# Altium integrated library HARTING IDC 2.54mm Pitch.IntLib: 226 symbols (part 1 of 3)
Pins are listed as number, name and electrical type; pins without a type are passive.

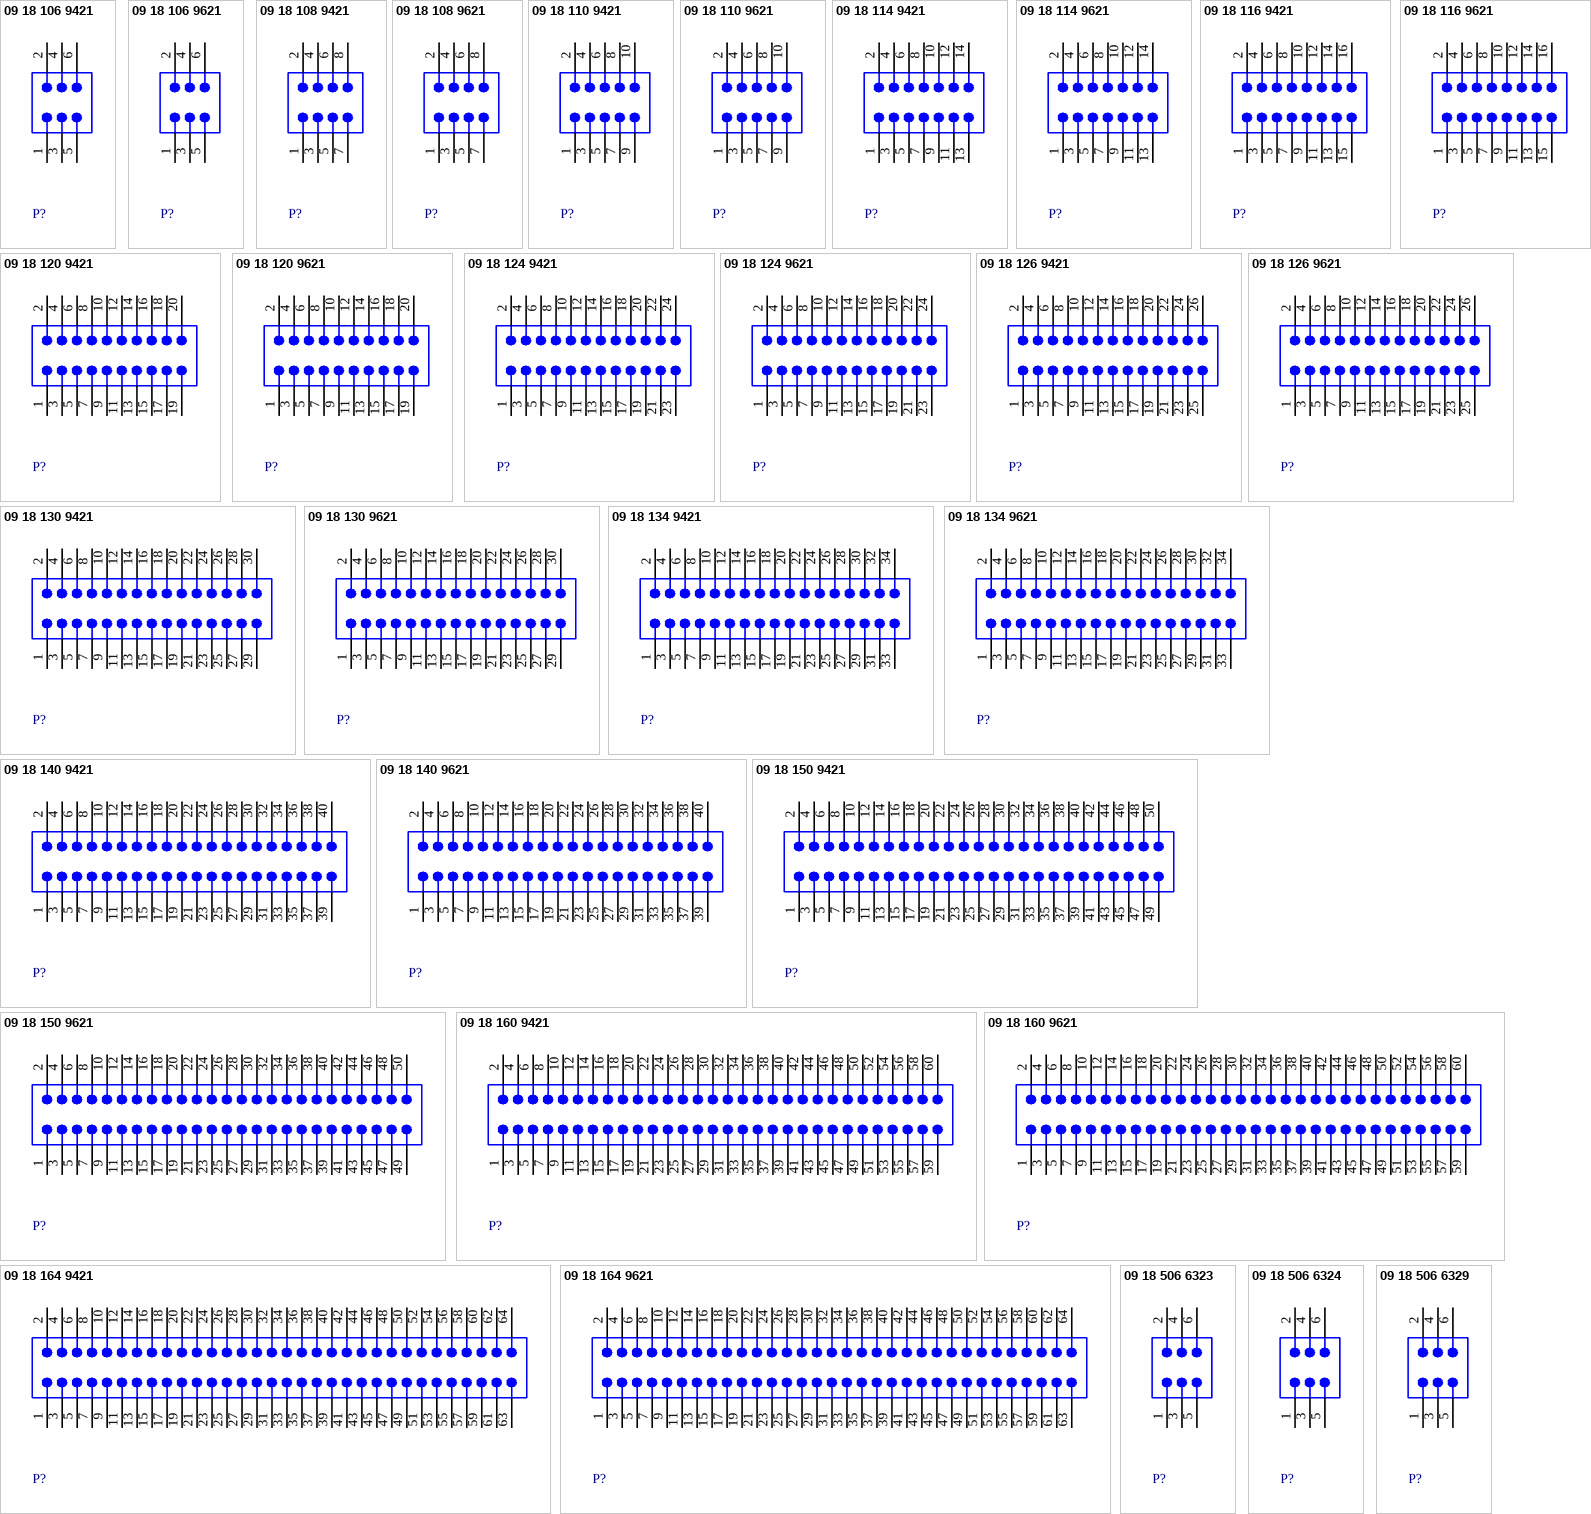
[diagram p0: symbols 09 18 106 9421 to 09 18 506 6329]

## 09 18 106 9421
designator P?
Flat Cable Connector (IDC), PCB Transition Connector, 2 Rows, Kinked Solder Pin, 6 Contacts; PCB_Layout: Complies with manufacturer's recommendation.; DrillSize: Corresponds to nominal value.
footprint 9181069421 (Connector; IDC, PCB Transition - 2 Rows, Thru-Hole; 6 Position; Vertical; Pitch 2.54 mm; Body 12.92 x 6.1 x 7.45 mm (LxWxH), Kinked Contacts)
pins: 1, 2, 3, 4, 5, 6

## 09 18 106 9621
designator P?
Flat Cable Connector (IDC), PCB Transition Connector, 2 Rows, Solder Pin, 6 Contacts; PCB_Layout: Complies with manufacturer's recommendation.; DrillSize: Corresponds to nominal value.
footprint 9181069621 (Connector; IDC, PCB Transition - 2 Rows, Thru-Hole; 6 Position; Vertical; Pitch 2.54 mm; Body 12.92 x 6.1 x 7.45 mm (LxWxH))
pins: 1, 2, 3, 4, 5, 6

## 09 18 108 9421
designator P?
Flat Cable Connector (IDC), PCB Transition Connector, 2 Rows, Kinked Solder Pin, 8 Contacts; PCB_Layout: Complies with manufacturer's recommendation.; DrillSize: Corresponds to nominal value.
footprint 9181089421 (Connector; IDC, PCB Transition - 2 Rows, Thru-Hole; 8 Position; Vertical; Pitch 2.54 mm; Body 15.46 x 6.1 x 7.45 mm (LxWxH), Kinked Contacts)
pins: 1, 2, 3, 4, 5, 6, 7, 8

## 09 18 108 9621
designator P?
Flat Cable Connector (IDC), PCB Transition Connector, 2 Rows, Solder Pin, 8 Contacts; PCB_Layout: Complies with manufacturer's recommendation.; DrillSize: Corresponds to nominal value.
footprint 9181089621 (Connector; IDC, PCB Transition - 2 Rows, Thru-Hole; 8 Position; Vertical; Pitch 2.54 mm; Body 15.46 x 6.1 x 7.45 mm (LxWxH))
pins: 1, 2, 3, 4, 5, 6, 7, 8

## 09 18 110 9421
designator P?
Flat Cable Connector (IDC), PCB Transition Connector, 2 Rows, Kinked Solder Pin, 10 Contacts; PCB_Layout: Complies with manufacturer's recommendation.; DrillSize: Corresponds to nominal value.
footprint 9181109421 (Connector; IDC, PCB Transition - 2 Rows, Thru-Hole; 10 Position; Vertical; Pitch 2.54 mm; Body 18.00 x 6.1 x 7.45 mm (LxWxH), Kinked Contacts)
pins: 1, 2, 3, 4, 5, 6, 7, 8, 9, 10

## 09 18 110 9621
designator P?
Flat Cable Connector (IDC), PCB Transition Connector, 2 Rows, Solder Pin, 10 Contacts; PCB_Layout: Complies with manufacturer's recommendation.; DrillSize: Corresponds to nominal value.
footprint 9181109621 (Connector; IDC, PCB Transition - 2 Rows, Thru-Hole; 10 Position; Vertical; Pitch 2.54 mm; Body 18.00 x 6.1 x 7.45 mm (LxWxH))
pins: 1, 2, 3, 4, 5, 6, 7, 8, 9, 10

## 09 18 114 9421
designator P?
Flat Cable Connector (IDC), PCB Transition Connector, 2 Rows, Kinked Solder Pin, 14 Contacts; PCB_Layout: Complies with manufacturer's recommendation.; DrillSize: Corresponds to nominal value.
footprint 9181149421 (Connector; IDC, PCB Transition - 2 Rows, Thru-Hole; 14 Position; Vertical; Pitch 2.54 mm; Body 23.08 x 6.1 x 7.45 mm (LxWxH), Kinked Contacts)
pins: 1, 2, 3, 4, 5, 6, 7, 8, 9, 10, 11, 12, 13, 14

## 09 18 114 9621
designator P?
Flat Cable Connector (IDC), PCB Transition Connector, 2 Rows, Solder Pin, 14 Contacts; PCB_Layout: Complies with manufacturer's recommendation.; DrillSize: Corresponds to nominal value.
footprint 9181149621 (Connector; IDC, PCB Transition - 2 Rows, Thru-Hole; 14 Position; Vertical; Pitch 2.54 mm; Body 23.08 x 6.1 x 7.45 mm (LxWxH))
pins: 1, 2, 3, 4, 5, 6, 7, 8, 9, 10, 11, 12, 13, 14

## 09 18 116 9421
designator P?
Flat Cable Connector (IDC), PCB Transition Connector, 2 Rows, Kinked Solder Pin, 16 Contacts; PCB_Layout: Complies with manufacturer's recommendation.; DrillSize: Corresponds to nominal value.
footprint 9181169421 (Connector; IDC, PCB Transition - 2 Rows, Thru-Hole; 16 Position; Vertical; Pitch 2.54 mm; Body 25.62 x 6.1 x 7.45 mm (LxWxH), Kinked Contacts)
pins: 1, 2, 3, 4, 5, 6, 7, 8, 9, 10, 11, 12, 13, 14, 15, 16

## 09 18 116 9621
designator P?
Flat Cable Connector (IDC), PCB Transition Connector, 2 Rows, Solder Pin, 16 Contacts; PCB_Layout: Complies with manufacturer's recommendation.; DrillSize: Corresponds to nominal value.
footprint 9181169621 (Connector; IDC, PCB Transition - 2 Rows, Thru-Hole; 16 Position; Vertical; Pitch 2.54 mm; Body 25.62 x 6.1 x 7.45 mm (LxWxH))
pins: 1, 2, 3, 4, 5, 6, 7, 8, 9, 10, 11, 12, 13, 14, 15, 16

## 09 18 120 9421
designator P?
Flat Cable Connector (IDC), PCB Transition Connector, 2 Rows, Kinked Solder Pin, 20 Contacts; PCB_Layout: Complies with manufacturer's recommendation.; DrillSize: Corresponds to nominal value.
footprint 9181209421 (Connector; IDC, PCB Transition - 2 Rows, Thru-Hole; 20 Position; Vertical; Pitch 2.54 mm; Body 30.74 x 6.1 x 7.45 mm (LxWxH), Kinked Contacts)
pins: 1, 2, 3, 4, 5, 6, 7, 8, 9, 10, 11, 12, 13, 14, 15, 16, 17, 18, 19, 20

## 09 18 120 9621
designator P?
Flat Cable Connector (IDC), PCB Transition Connector, 2 Rows, Solder Pin, 20 Contacts; PCB_Layout: Complies with manufacturer's recommendation.; DrillSize: Corresponds to nominal value.
footprint 9181209621 (Connector; IDC, PCB Transition - 2 Rows, Thru-Hole; 20 Position; Vertical; Pitch 2.54 mm; Body 30.74 x 6.1 x 7.45 mm (LxWxH))
pins: 1, 2, 3, 4, 5, 6, 7, 8, 9, 10, 11, 12, 13, 14, 15, 16, 17, 18, 19, 20

## 09 18 124 9421
designator P?
Flat Cable Connector (IDC), PCB Transition Connector, 2 Rows, Kinked Solder Pin, 24 Contacts; PCB_Layout: Complies with manufacturer's recommendation.; DrillSize: Corresponds to nominal value.
footprint 9181249421 (Connector; IDC, PCB Transition - 2 Rows, Thru-Hole; 24 Position; Vertical; Pitch 2.54 mm; Body 35.78 x 6.1 x 7.45 mm (LxWxH), Kinked Contacts)
pins: 1, 2, 3, 4, 5, 6, 7, 8, 9, 10, 11, 12, 13, 14, 15, 16, 17, 18, 19, 20, 21, 22, 23, 24

## 09 18 124 9621
designator P?
Flat Cable Connector (IDC), PCB Transition Connector, 2 Rows, Solder Pin, 24 Contacts; PCB_Layout: Complies with manufacturer's recommendation.; DrillSize: Corresponds to nominal value.
footprint 9181249621 (Connector; IDC, PCB Transition - 2 Rows, Thru-Hole; 24 Position; Vertical; Pitch 2.54 mm; Body 35.78 x 6.1 x 7.45 mm (LxWxH))
pins: 1, 2, 3, 4, 5, 6, 7, 8, 9, 10, 11, 12, 13, 14, 15, 16, 17, 18, 19, 20, 21, 22, 23, 24

## 09 18 126 9421
designator P?
Flat Cable Connector (IDC), PCB Transition Connector, 2 Rows, Kinked Solder Pin, 26 Contacts; PCB_Layout: Complies with manufacturer's recommendation.; DrillSize: Corresponds to nominal value.
footprint 9181269421 (Connector; IDC, PCB Transition - 2 Rows, Thru-Hole; 26 Position; Vertical; Pitch 2.54 mm; Body 38.32 x 6.1 x 7.45 mm (LxWxH), Kinked Contacts)
pins: 1, 2, 3, 4, 5, 6, 7, 8, 9, 10, 11, 12, 13, 14, 15, 16, 17, 18, 19, 20, 21, 22, 23, 24, 25, 26

## 09 18 126 9621
designator P?
Flat Cable Connector (IDC), PCB Transition Connector, 2 Rows, Solder Pin, 26 Contacts; PCB_Layout: Complies with manufacturer's recommendation.; DrillSize: Corresponds to nominal value.
footprint 9181269621 (Connector; IDC, PCB Transition - 2 Rows, Thru-Hole; 26 Position; Vertical; Pitch 2.54 mm; Body 38.32 x 6.1 x 7.45 mm (LxWxH))
pins: 1, 2, 3, 4, 5, 6, 7, 8, 9, 10, 11, 12, 13, 14, 15, 16, 17, 18, 19, 20, 21, 22, 23, 24, 25, 26

## 09 18 130 9421
designator P?
Flat Cable Connector (IDC), PCB Transition Connector, 2 Rows, Kinked Solder Pin, 30 Contacts; PCB_Layout: Complies with manufacturer's recommendation.; DrillSize: Corresponds to nominal value.
footprint 9181309421 (Connector; IDC, PCB Transition - 2 Rows, Thru-Hole; 30 Position; Vertical; Pitch 2.54 mm; Body 43.40 x 6.1 x 7.45 mm (LxWxH), Kinked Contacts)
pins: 1, 2, 3, 4, 5, 6, 7, 8, 9, 10, 11, 12, 13, 14, 15, 16, 17, 18, 19, 20, 21, 22, 23, 24, 25, 26, 27, 28, 29, 30

## 09 18 130 9621
designator P?
Flat Cable Connector (IDC), PCB Transition Connector, 2 Rows, Solder Pin, 30 Contacts; PCB_Layout: Complies with manufacturer's recommendation.; DrillSize: Corresponds to nominal value.
footprint 9181309621 (Connector; IDC, PCB Transition - 2 Rows, Thru-Hole; 30 Position; Vertical; Pitch 2.54 mm; Body 43.40 x 6.1 x 7.45 mm (LxWxH))
pins: 1, 2, 3, 4, 5, 6, 7, 8, 9, 10, 11, 12, 13, 14, 15, 16, 17, 18, 19, 20, 21, 22, 23, 24, 25, 26, 27, 28, 29, 30

## 09 18 134 9421
designator P?
Flat Cable Connector (IDC), PCB Transition Connector, 2 Rows, Kinked Solder Pin, 34 Contacts; PCB_Layout: Complies with manufacturer's recommendation.; DrillSize: Corresponds to nominal value.
footprint 9181349421 (Connector; IDC, PCB Transition - 2 Rows, Thru-Hole; 34 Position; Vertical; Pitch 2.54 mm; Body 48.48 x 6.1 x 7.45 mm (LxWxH), Kinked Contacts)
pins: 1, 2, 3, 4, 5, 6, 7, 8, 9, 10, 11, 12, 13, 14, 15, 16, 17, 18, 19, 20, 21, 22, 23, 24, 25, 26, 27, 28, 29, 30, 31, 32, 33, 34

## 09 18 134 9621
designator P?
Flat Cable Connector (IDC), PCB Transition Connector, 2 Rows, Solder Pin, 34 Contacts; PCB_Layout: Complies with manufacturer's recommendation.; DrillSize: Corresponds to nominal value.
footprint 9181349621 (Connector; IDC, PCB Transition - 2 Rows, Thru-Hole; 34 Position; Vertical; Pitch 2.54 mm; Body 48.48 x 6.1 x 7.45 mm (LxWxH))
pins: 1, 2, 3, 4, 5, 6, 7, 8, 9, 10, 11, 12, 13, 14, 15, 16, 17, 18, 19, 20, 21, 22, 23, 24, 25, 26, 27, 28, 29, 30, 31, 32, 33, 34

## 09 18 140 9421
designator P?
Flat Cable Connector (IDC), PCB Transition Connector, 2 Rows, Kinked Solder Pin, 40 Contacts; PCB_Layout: Complies with manufacturer's recommendation.; DrillSize: Corresponds to nominal value.
footprint 9181409421 (Connector; IDC, PCB Transition - 2 Rows, Thru-Hole; 40 Position; Vertical; Pitch 2.54 mm; Body 56.10 x 6.1 x 7.45 mm (LxWxH), Kinked Contacts)
pins: 1, 2, 3, 4, 5, 6, 7, 8, 9, 10, 11, 12, 13, 14, 15, 16, 17, 18, 19, 20, 21, 22, 23, 24, 25, 26, 27, 28, 29, 30, 31, 32, 33, 34, 35, 36, 37, 38, 39, 40

## 09 18 140 9621
designator P?
Flat Cable Connector (IDC), PCB Transition Connector, 2 Rows, Solder Pin, 40 Contacts; PCB_Layout: Complies with manufacturer's recommendation.; DrillSize: Corresponds to nominal value.
footprint 9181409621 (Connector; IDC, PCB Transition - 2 Rows, Thru-Hole; 40 Position; Vertical; Pitch 2.54 mm; Body 56.10 x 6.1 x 7.45 mm (LxWxH))
pins: 1, 2, 3, 4, 5, 6, 7, 8, 9, 10, 11, 12, 13, 14, 15, 16, 17, 18, 19, 20, 21, 22, 23, 24, 25, 26, 27, 28, 29, 30, 31, 32, 33, 34, 35, 36, 37, 38, 39, 40

## 09 18 150 9421
designator P?
Flat Cable Connector (IDC), PCB Transition Connector, 2 Rows, Kinked Solder Pin, 50 Contacts; PCB_Layout: Complies with manufacturer's recommendation.; DrillSize: Corresponds to nominal value.
footprint 9181509421 (Connector; IDC, PCB Transition - 2 Rows, Thru-Hole; 50 Position; Vertical; Pitch 2.54 mm; Body 68.80 x 6.1 x 7.45 mm (LxWxH), Kinked Contacts)
pins: 1, 2, 3, 4, 5, 6, 7, 8, 9, 10, 11, 12, 13, 14, 15, 16, 17, 18, 19, 20, 21, 22, 23, 24, 25, 26, 27, 28, 29, 30, 31, 32, 33, 34, 35, 36, 37, 38, 39, 40, 41, 42, 43, 44, 45, 46, 47, 48, 49, 50

## 09 18 150 9621
designator P?
Flat Cable Connector (IDC), PCB Transition Connector, 2 Rows, Solder Pin, 50 Contacts; PCB_Layout: Complies with manufacturer's recommendation.; DrillSize: Corresponds to nominal value.
footprint 9181509621 (Connector; IDC, PCB Transition - 2 Rows, Thru-Hole; 50 Position; Vertical; Pitch 2.54 mm; Body 68.80 x 6.1 x 7.45 mm (LxWxH))
pins: 1, 2, 3, 4, 5, 6, 7, 8, 9, 10, 11, 12, 13, 14, 15, 16, 17, 18, 19, 20, 21, 22, 23, 24, 25, 26, 27, 28, 29, 30, 31, 32, 33, 34, 35, 36, 37, 38, 39, 40, 41, 42, 43, 44, 45, 46, 47, 48, 49, 50

## 09 18 160 9421
designator P?
Flat Cable Connector (IDC), PCB Transition Connector, 2 Rows, Kinked Solder Pin, 60 Contacts; PCB_Layout: Complies with manufacturer's recommendation.; DrillSize: Corresponds to nominal value.
footprint 9181609421 (Connector; IDC, PCB Transition - 2 Rows, Thru-Hole; 60 Position; Vertical; Pitch 2.54 mm; Body 81.50 x 6.1 x 7.45 mm (LxWxH), Kinked Contacts)
pins: 1, 2, 3, 4, 5, 6, 7, 8, 9, 10, 11, 12, 13, 14, 15, 16, 17, 18, 19, 20, 21, 22, 23, 24, 25, 26, 27, 28, 29, 30, 31, 32, 33, 34, 35, 36, 37, 38, 39, 40, 41, 42, 43, 44, 45, 46, 47, 48, 49, 50, 51, 52, 53, 54, 55, 56, 57, 58, 59, 60

## 09 18 160 9621
designator P?
Flat Cable Connector (IDC), PCB Transition Connector, 2 Rows, Solder Pin, 60 Contacts; PCB_Layout: Complies with manufacturer's recommendation.; DrillSize: Corresponds to nominal value.
footprint 9181609621 (Connector; IDC, PCB Transition - 2 Rows, Thru-Hole; 60 Position; Vertical; Pitch 2.54 mm; Body 81.50 x 6.1 x 7.45 mm (LxWxH))
pins: 1, 2, 3, 4, 5, 6, 7, 8, 9, 10, 11, 12, 13, 14, 15, 16, 17, 18, 19, 20, 21, 22, 23, 24, 25, 26, 27, 28, 29, 30, 31, 32, 33, 34, 35, 36, 37, 38, 39, 40, 41, 42, 43, 44, 45, 46, 47, 48, 49, 50, 51, 52, 53, 54, 55, 56, 57, 58, 59, 60

## 09 18 164 9421
designator P?
Flat Cable Connector (IDC), PCB Transition Connector, 2 Rows, Kinked Solder Pin, 64 Contacts; PCB_Layout: Complies with manufacturer's recommendation.; DrillSize: Corresponds to nominal value.
footprint 9181649421 (Connector; IDC, PCB Transition - 2 Rows, Thru-Hole; 64 Position; Vertical; Pitch 2.54 mm; Body 86.58 x 6.1 x 7.45 mm (LxWxH), Kinked Contacts)
pins: 1, 2, 3, 4, 5, 6, 7, 8, 9, 10, 11, 12, 13, 14, 15, 16, 17, 18, 19, 20, 21, 22, 23, 24, 25, 26, 27, 28, 29, 30, 31, 32, 33, 34, 35, 36, 37, 38, 39, 40, 41, 42, 43, 44, 45, 46, 47, 48, 49, 50, 51, 52, 53, 54, 55, 56, 57, 58, 59, 60, 61, 62, 63, 64

## 09 18 164 9621
designator P?
Flat Cable Connector (IDC), PCB Transition Connector, 2 Rows, Solder Pin, 64 Contacts; PCB_Layout: Complies with manufacturer's recommendation.; DrillSize: Corresponds to nominal value.
footprint 9181649621 (Connector; IDC, PCB Transition - 2 Rows, Thru-Hole; 64 Position; Vertical; Pitch 2.54 mm; Body 86.58 x 6.1 x 7.45 mm (LxWxH))
pins: 1, 2, 3, 4, 5, 6, 7, 8, 9, 10, 11, 12, 13, 14, 15, 16, 17, 18, 19, 20, 21, 22, 23, 24, 25, 26, 27, 28, 29, 30, 31, 32, 33, 34, 35, 36, 37, 38, 39, 40, 41, 42, 43, 44, 45, 46, 47, 48, 49, 50, 51, 52, 53, 54, 55, 56, 57, 58, 59, 60, 61, 62, 63, 64

## 09 18 506 6323
designator P?
Flat Cable Connector (IDC), Low-Profile Male Header, Angled Solder Pin, 6 Contacts, Performance Level 2; PCB_Layout: Complies with manufacturer's recommendation.; DrillSize: Corresponds to nominal value.
footprint 918506x323 (Connector; IDC, Low Profile Male Header, Thru-Hole; 6 Position; Right Angle; Pitch 2.54 mm; Body 15.24 x 8.9 x 9.2 mm (LxWxH))
pins: 1, 2, 3, 4, 5, 6

## 09 18 506 6324
designator P?
Flat Cable Connector (IDC), Low-Profile Male Header, Straight Solder Pin, 6 Contacts, Performance Level 2; PCB_Layout: Complies with manufacturer's recommendation.; DrillSize: Corresponds to nominal value.
footprint 918506x324 (Connector; IDC, Low Profile Male Header, Thru-Hole; 6 Position; Vertical; Pitch 2.54 mm; Body 15.24 x 9.2 x 9.45 mm (LxWxH))
pins: 1, 2, 3, 4, 5, 6

## 09 18 506 6329
designator P?
Flat Cable Connector (IDC), Standard Male Header, Straight Press-in Pin, 6 Contacts, Performance Level 2; PCB_Layout: Complies with manufacturer's recommendation.; DrillSize: Corresponds to nominal value.
footprint 918506x329 (Connector; IDC, Straight Press-in Pin, Thru-Hole; 6 Position; Vertical; Pitch 2.54 mm; Body 15.24 x 9.2 x 9.45 mm (LxWxH))
pins: 1, 2, 3, 4, 5, 6

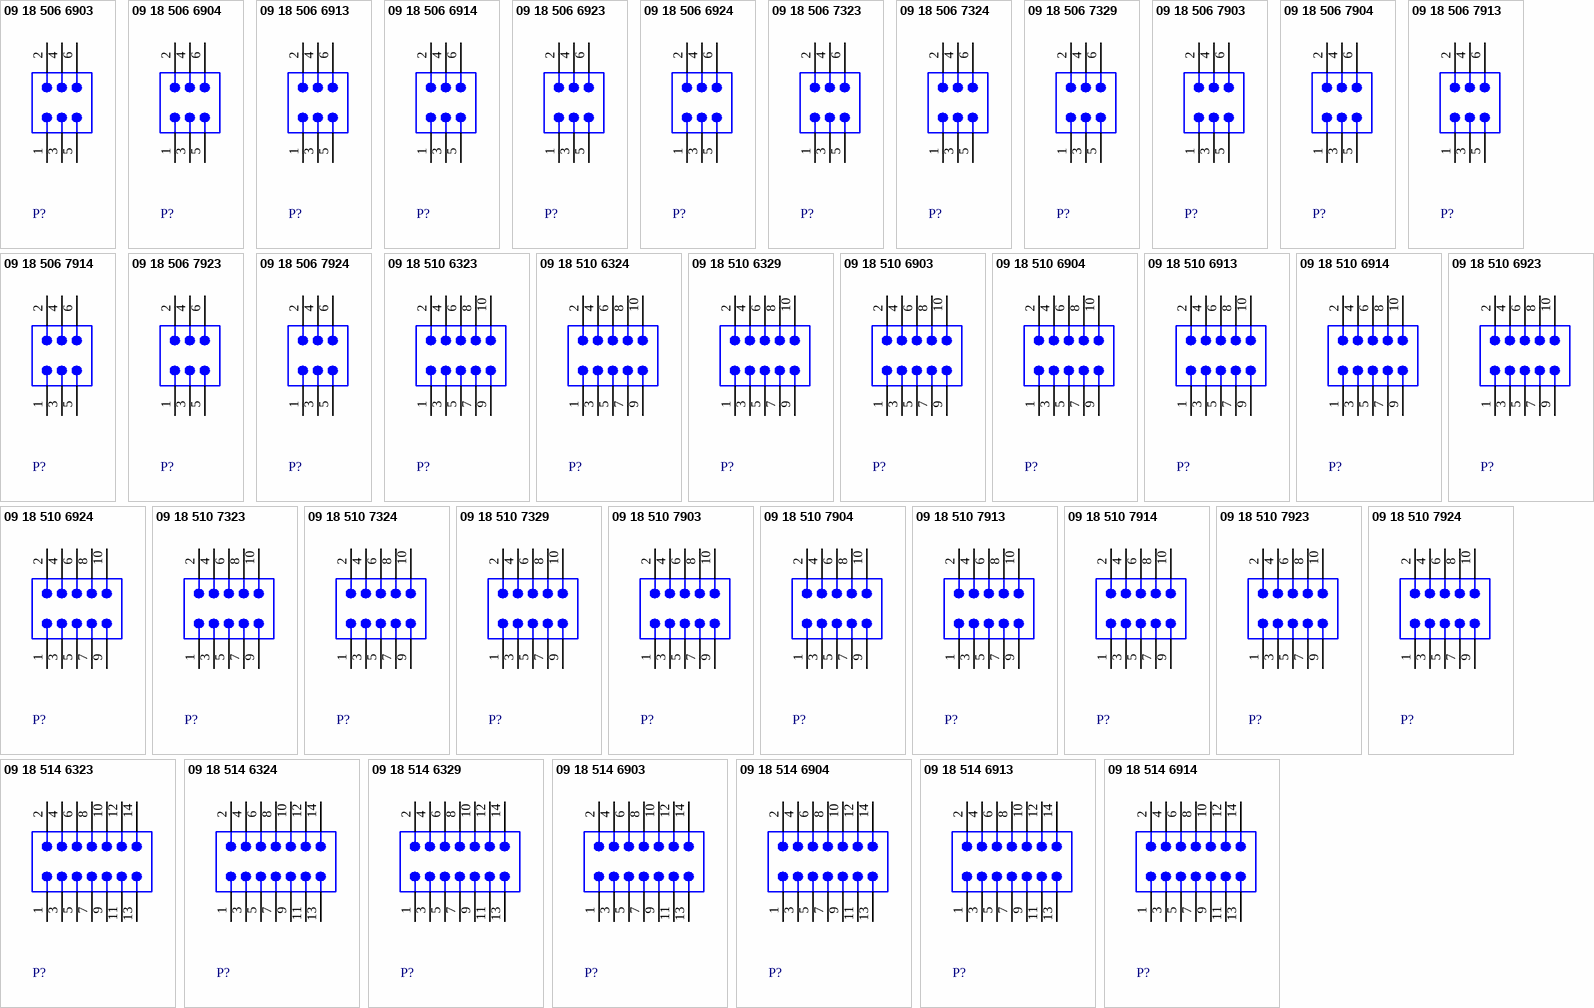
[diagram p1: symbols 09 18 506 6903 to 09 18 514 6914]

## 09 18 506 6903
designator P?
Flat Cable Connector (IDC), Standard Male Header, Angled Solder Pin, 6 Contacts, Long Levers, Performance Level 2; PCB_Layout: Complies with manufacturer's recommendation.; DrillSize: Corresponds to nominal value.
footprint 918506x903 (Connector; IDC, Thru-Hole; 6 Position; Right Angle; Pitch 2.54 mm; Body 27.10 x 8.5 x 25.75 mm (LxHxW), Locking levers)
signal-integrity model IDC
pins: 1, 2, 3, 4, 5, 6

## 09 18 506 6904
designator P?
Flat Cable Connector (IDC), Standard Male Header, Straight Solder Pin, 6 Contacts, Long Levers, Performance Level 2; PCB_Layout: Complies with manufacturer's recommendation.; DrillSize: Corresponds to nominal value.
footprint 918506x904 (Connector; IDC, Thru-Hole; 6 Position; Vertical; Pitch 2.54 mm; Body 27.10 x 8.5 x 25.75 mm (LxWxH), Locking levers)
pins: 1, 2, 3, 4, 5, 6

## 09 18 506 6913
designator P?
Flat Cable Connector (IDC), Standard Male Header, Angled Solder Pin, 6 Contacts, Short Levers, Performance Level 2; PCB_Layout: Complies with manufacturer's recommendation.; DrillSize: Corresponds to nominal value.
footprint 918506x913 (Connector; IDC, Thru-Hole; 6 Position; Right Angle; Pitch 2.54 mm; Body 26.90 x 8.5 x 23.30 mm (LxHxW), Locking levers)
pins: 1, 2, 3, 4, 5, 6

## 09 18 506 6914
designator P?
Flat Cable Connector (IDC), Standard Male Header, Straight Solder Pin, 6 Contacts, Short Levers, Performance Level 2; PCB_Layout: Complies with manufacturer's recommendation.; DrillSize: Corresponds to nominal value.
footprint 918506x914 (Connector; IDC, Thru-Hole; 6 Position; Vertical; Pitch 2.54 mm; Body 26.90 x 8.5 x 23.30 mm (LxWxH), Locking levers)
pins: 1, 2, 3, 4, 5, 6

## 09 18 506 6923
designator P?
Flat Cable Connector (IDC), Standard Male Header, Angled Solder Pin, 6 Contacts, Without Levers, Performance Level 2; PCB_Layout: Complies with manufacturer's recommendation.; DrillSize: Corresponds to nominal value.
footprint 918506x923 (Connector; IDC, Thru-Hole; 6 Position; Right Angle; Pitch 2.54 mm; Body 26.90 x 8.5 x 17.30 mm (LxHxW), Without locking levers)
pins: 1, 2, 3, 4, 5, 6

## 09 18 506 6924
designator P?
Flat Cable Connector (IDC), Standard Male Header, Straight Solder Pin, 6 Contacts, Without Levers, Performance Level 2; PCB_Layout: Complies with manufacturer's recommendation.; DrillSize: Corresponds to nominal value.
footprint 918506x924 (Connector; IDC, Thru-Hole; 6 Position; Vertical; Pitch 2.54 mm; Body 26.90 x 8.5 x 17.30 mm (LxWxH), Without locking levers)
pins: 1, 2, 3, 4, 5, 6

## 09 18 506 7323
designator P?
Flat Cable Connector (IDC), Low-Profile Male Header, Angled Solder Pin, 6 Contacts, Performance Level 3; PCB_Layout: Complies with manufacturer's recommendation.; DrillSize: Corresponds to nominal value.
footprint 918506x323 (Connector; IDC, Low Profile Male Header, Thru-Hole; 6 Position; Right Angle; Pitch 2.54 mm; Body 15.24 x 8.9 x 9.2 mm (LxWxH))
pins: 1, 2, 3, 4, 5, 6

## 09 18 506 7324
designator P?
Flat Cable Connector (IDC), Low-Profile Male Header, Straight Solder Pin, 6 Contacts, Performance Level 3; PCB_Layout: Complies with manufacturer's recommendation.; DrillSize: Corresponds to nominal value.
footprint 918506x324 (Connector; IDC, Low Profile Male Header, Thru-Hole; 6 Position; Vertical; Pitch 2.54 mm; Body 15.24 x 9.2 x 9.45 mm (LxWxH))
pins: 1, 2, 3, 4, 5, 6

## 09 18 506 7329
designator P?
Flat Cable Connector (IDC), Standard Male Header, Straight Press-in Pin, 6 Contacts, Performance Level 3; PCB_Layout: Complies with manufacturer's recommendation.; DrillSize: Corresponds to nominal value.
footprint 918506x329 (Connector; IDC, Straight Press-in Pin, Thru-Hole; 6 Position; Vertical; Pitch 2.54 mm; Body 15.24 x 9.2 x 9.45 mm (LxWxH))
pins: 1, 2, 3, 4, 5, 6

## 09 18 506 7903
designator P?
Flat Cable Connector (IDC), Standard Male Header, Angled Solder Pin, 6 Contacts, Long Levers, Performance Level 3; PCB_Layout: Complies with manufacturer's recommendation.; DrillSize: Corresponds to nominal value.
footprint 918506x903 (Connector; IDC, Thru-Hole; 6 Position; Right Angle; Pitch 2.54 mm; Body 27.10 x 8.5 x 25.75 mm (LxHxW), Locking levers)
pins: 1, 2, 3, 4, 5, 6

## 09 18 506 7904
designator P?
Flat Cable Connector (IDC), Standard Male Header, Straight Solder Pin, 6 Contacts, Long Levers, Performance Level 3; PCB_Layout: Complies with manufacturer's recommendation.; DrillSize: Corresponds to nominal value.
footprint 918506x904 (Connector; IDC, Thru-Hole; 6 Position; Vertical; Pitch 2.54 mm; Body 27.10 x 8.5 x 25.75 mm (LxWxH), Locking levers)
pins: 1, 2, 3, 4, 5, 6

## 09 18 506 7913
designator P?
Flat Cable Connector (IDC), Standard Male Header, Angled Solder Pin, 6 Contacts, Short Levers, Performance Level 3; PCB_Layout: Complies with manufacturer's recommendation.; DrillSize: Corresponds to nominal value.
footprint 918506x913 (Connector; IDC, Thru-Hole; 6 Position; Right Angle; Pitch 2.54 mm; Body 26.90 x 8.5 x 23.30 mm (LxHxW), Locking levers)
pins: 1, 2, 3, 4, 5, 6

## 09 18 506 7914
designator P?
Flat Cable Connector (IDC), Standard Male Header, Straight Solder Pin, 6 Contacts, Short Levers, Performance Level 3; PCB_Layout: Complies with manufacturer's recommendation.; DrillSize: Corresponds to nominal value.
footprint 918506x914 (Connector; IDC, Thru-Hole; 6 Position; Vertical; Pitch 2.54 mm; Body 26.90 x 8.5 x 23.30 mm (LxWxH), Locking levers)
pins: 1, 2, 3, 4, 5, 6

## 09 18 506 7923
designator P?
Flat Cable Connector (IDC), Standard Male Header, Angled Solder Pin, 6 Contacts, Without Levers, Performance Level 3; PCB_Layout: Complies with manufacturer's recommendation.; DrillSize: Corresponds to nominal value.
footprint 918506x923 (Connector; IDC, Thru-Hole; 6 Position; Right Angle; Pitch 2.54 mm; Body 26.90 x 8.5 x 17.30 mm (LxHxW), Without locking levers)
pins: 1, 2, 3, 4, 5, 6

## 09 18 506 7924
designator P?
Flat Cable Connector (IDC), Standard Male Header, Straight Solder Pin, 6 Contacts, Without Levers, Performance Level 3; PCB_Layout: Complies with manufacturer's recommendation.; DrillSize: Corresponds to nominal value.
footprint 918506x924 (Connector; IDC, Thru-Hole; 6 Position; Vertical; Pitch 2.54 mm; Body 26.90 x 8.5 x 17.30 mm (LxWxH), Without locking levers)
pins: 1, 2, 3, 4, 5, 6

## 09 18 510 6323
designator P?
Flat Cable Connector (IDC), Low-Profile Male Header, Angled Solder Pin, 10 Contacts, Performance Level 2; PCB_Layout: Complies with manufacturer's recommendation.; DrillSize: Corresponds to nominal value.
footprint 918510x323 (Connector; IDC, Low Profile Male Header, Thru-Hole; 10 Position; Right Angle; Pitch 2.54 mm; Body 20.32 x 8.9 x 9.2 mm (LxWxH))
pins: 1, 2, 3, 4, 5, 6, 7, 8, 9, 10

## 09 18 510 6324
designator P?
Flat Cable Connector (IDC), Low-Profile Male Header, Straight Solder Pin, 10 Contacts, Performance Level 2; PCB_Layout: Complies with manufacturer's recommendation.; DrillSize: Corresponds to nominal value.
footprint 918510x324 (Connector; IDC, Low Profile Male Header, Thru-Hole; 10 Position; Vertical; Pitch 2.54 mm; Body 20.32 x 9.2 x 9.45 mm (LxWxH))
pins: 1, 2, 3, 4, 5, 6, 7, 8, 9, 10

## 09 18 510 6329
designator P?
Flat Cable Connector (IDC), Standard Male Header, Straight Press-in Pin, 10 Contacts, Performance Level 2; PCB_Layout: Complies with manufacturer's recommendation.; DrillSize: Corresponds to nominal value.
footprint 918510x329 (Connector; IDC, Straight Press-in Pin, Thru-Hole; 10 Position; Vertical; Pitch 2.54 mm; Body 20.32 x 9.2 x 9.45 mm (LxWxH))
pins: 1, 2, 3, 4, 5, 6, 7, 8, 9, 10

## 09 18 510 6903
designator P?
Flat Cable Connector (IDC), Standard Male Header, Angled Solder Pin, 10 Contacts, Long Levers, Performance Level 2; PCB_Layout: Complies with manufacturer's recommendation.; DrillSize: Corresponds to nominal value.
footprint 918510x903 (Connector; IDC, Thru-Hole; 10 Position; Right Angle; Pitch 2.54 mm; Body 32.30 x 8.5 x 25.75 mm (LxHxW), Locking levers)
pins: 1, 2, 3, 4, 5, 6, 7, 8, 9, 10

## 09 18 510 6904
designator P?
Flat Cable Connector (IDC), Standard Male Header, Straight Solder Pin, 10 Contacts, Long Levers, Performance Level 2; PCB_Layout: Complies with manufacturer's recommendation.; DrillSize: Corresponds to nominal value.
footprint 918510x904 (Connector; IDC, Thru-Hole; 10 Position; Vertical; Pitch 2.54 mm; Body 32.30 x 8.5 x 25.75 mm (LxWxH), Locking levers)
pins: 1, 2, 3, 4, 5, 6, 7, 8, 9, 10

## 09 18 510 6913
designator P?
Flat Cable Connector (IDC), Standard Male Header, Angled Solder Pin, 10 Contacts, Short Levers, Performance Level 2; PCB_Layout: Complies with manufacturer's recommendation.; DrillSize: Corresponds to nominal value.
footprint 918510x913 (Connector; IDC, Thru-Hole; 10 Position; Right Angle; Pitch 2.54 mm; Body 32.30 x 8.5 x 23.30 mm (LxHxW), Locking levers)
pins: 1, 2, 3, 4, 5, 6, 7, 8, 9, 10

## 09 18 510 6914
designator P?
Flat Cable Connector (IDC), Standard Male Header, Straight Solder Pin, 10 Contacts, Short Levers, Performance Level 2; PCB_Layout: Complies with manufacturer's recommendation.; DrillSize: Corresponds to nominal value.
footprint 918510x914 (Connector; IDC, Thru-Hole; 10 Position; Vertical; Pitch 2.54 mm; Body 32.30 x 8.5 x 23.30 mm (LxWxH), Locking levers)
pins: 1, 2, 3, 4, 5, 6, 7, 8, 9, 10

## 09 18 510 6923
designator P?
Flat Cable Connector (IDC), Standard Male Header, Angled Solder Pin, 10 Contacts, Without Levers, Performance Level 2; PCB_Layout: Complies with manufacturer's recommendation.; DrillSize: Corresponds to nominal value.
footprint 918510x923 (Connector; IDC, Thru-Hole; 10 Position; Right Angle; Pitch 2.54 mm; Body 32.30 x 8.5 x 17.30 mm (LxHxW), Without locking levers)
pins: 1, 2, 3, 4, 5, 6, 7, 8, 9, 10

## 09 18 510 6924
designator P?
Flat Cable Connector (IDC), Standard Male Header, Straight Solder Pin, 10 Contacts, Without Levers, Performance Level 2; PCB_Layout: Complies with manufacturer's recommendation.; DrillSize: Corresponds to nominal value.
footprint 918510x924 (Connector; IDC, Thru-Hole; 10 Position; Vertical; Pitch 2.54 mm; Body 32.30 x 8.5 x 17.30 mm (LxWxH), Without locking levers)
pins: 1, 2, 3, 4, 5, 6, 7, 8, 9, 10

## 09 18 510 7323
designator P?
Flat Cable Connector (IDC), Low-Profile Male Header, Angled Solder Pin, 10 Contacts, Performance Level 3; PCB_Layout: Complies with manufacturer's recommendation.; DrillSize: Corresponds to nominal value.
footprint 918510x323 (Connector; IDC, Low Profile Male Header, Thru-Hole; 10 Position; Right Angle; Pitch 2.54 mm; Body 20.32 x 8.9 x 9.2 mm (LxWxH))
pins: 1, 2, 3, 4, 5, 6, 7, 8, 9, 10

## 09 18 510 7324
designator P?
Flat Cable Connector (IDC), Low-Profile Male Header, Straight Solder Pin, 10 Contacts, Performance Level 3; PCB_Layout: Complies with manufacturer's recommendation.; DrillSize: Corresponds to nominal value.
footprint 918510x324 (Connector; IDC, Low Profile Male Header, Thru-Hole; 10 Position; Vertical; Pitch 2.54 mm; Body 20.32 x 9.2 x 9.45 mm (LxWxH))
pins: 1, 2, 3, 4, 5, 6, 7, 8, 9, 10

## 09 18 510 7329
designator P?
Flat Cable Connector (IDC), Standard Male Header, Straight Press-in Pin, 10 Contacts, Performance Level 3; PCB_Layout: Complies with manufacturer's recommendation.; DrillSize: Corresponds to nominal value.
footprint 918510x329 (Connector; IDC, Straight Press-in Pin, Thru-Hole; 10 Position; Vertical; Pitch 2.54 mm; Body 20.32 x 9.2 x 9.45 mm (LxWxH))
pins: 1, 2, 3, 4, 5, 6, 7, 8, 9, 10

## 09 18 510 7903
designator P?
Flat Cable Connector (IDC), Standard Male Header, Angled Solder Pin, 10 Contacts, Long Levers, Performance Level 3; PCB_Layout: Complies with manufacturer's recommendation.; DrillSize: Corresponds to nominal value.
footprint 918510x903 (Connector; IDC, Thru-Hole; 10 Position; Right Angle; Pitch 2.54 mm; Body 32.30 x 8.5 x 25.75 mm (LxHxW), Locking levers)
pins: 1, 2, 3, 4, 5, 6, 7, 8, 9, 10

## 09 18 510 7904
designator P?
Flat Cable Connector (IDC), Standard Male Header, Straight Solder Pin, 10 Contacts, Long Levers, Performance Level 3; PCB_Layout: Complies with manufacturer's recommendation.; DrillSize: Corresponds to nominal value.
footprint 918510x904 (Connector; IDC, Thru-Hole; 10 Position; Vertical; Pitch 2.54 mm; Body 32.30 x 8.5 x 25.75 mm (LxWxH), Locking levers)
pins: 1, 2, 3, 4, 5, 6, 7, 8, 9, 10

## 09 18 510 7913
designator P?
Flat Cable Connector (IDC), Standard Male Header, Angled Solder Pin, 10 Contacts, Short Levers, Performance Level 3; PCB_Layout: Complies with manufacturer's recommendation.; DrillSize: Corresponds to nominal value.
footprint 918510x913 (Connector; IDC, Thru-Hole; 10 Position; Right Angle; Pitch 2.54 mm; Body 32.30 x 8.5 x 23.30 mm (LxHxW), Locking levers)
pins: 1, 2, 3, 4, 5, 6, 7, 8, 9, 10

## 09 18 510 7914
designator P?
Flat Cable Connector (IDC), Standard Male Header, Straight Solder Pin, 10 Contacts, Short Levers, Performance Level 3; PCB_Layout: Complies with manufacturer's recommendation.; DrillSize: Corresponds to nominal value.
footprint 918510x914 (Connector; IDC, Thru-Hole; 10 Position; Vertical; Pitch 2.54 mm; Body 32.30 x 8.5 x 23.30 mm (LxWxH), Locking levers)
pins: 1, 2, 3, 4, 5, 6, 7, 8, 9, 10

## 09 18 510 7923
designator P?
Flat Cable Connector (IDC), Standard Male Header, Angled Solder Pin, 10 Contacts, Without Levers, Performance Level 3; PCB_Layout: Complies with manufacturer's recommendation.; DrillSize: Corresponds to nominal value.
footprint 918510x923 (Connector; IDC, Thru-Hole; 10 Position; Right Angle; Pitch 2.54 mm; Body 32.30 x 8.5 x 17.30 mm (LxHxW), Without locking levers)
pins: 1, 2, 3, 4, 5, 6, 7, 8, 9, 10

## 09 18 510 7924
designator P?
Flat Cable Connector (IDC), Standard Male Header, Straight Solder Pin, 10 Contacts, Without Levers, Performance Level 3; PCB_Layout: Complies with manufacturer's recommendation.; DrillSize: Corresponds to nominal value.
footprint 918510x924 (Connector; IDC, Thru-Hole; 10 Position; Vertical; Pitch 2.54 mm; Body 32.30 x 8.5 x 17.30 mm (LxWxH), Without locking levers)
pins: 1, 2, 3, 4, 5, 6, 7, 8, 9, 10

## 09 18 514 6323
designator P?
Flat Cable Connector (IDC), Low-Profile Male Header, Angled Solder Pin, 14 Contacts, Performance Level 2; PCB_Layout: Complies with manufacturer's recommendation.; DrillSize: Corresponds to nominal value.
footprint 918514x323 (Connector; IDC, Low Profile Male Header, Thru-Hole; 14 Position; Right Angle; Pitch 2.54 mm; Body 25.40 x 8.9 x 9.2 mm (LxWxH))
pins: 1, 2, 3, 4, 5, 6, 7, 8, 9, 10, 11, 12, 13, 14

## 09 18 514 6324
designator P?
Flat Cable Connector (IDC), Low-Profile Male Header, Straight Solder Pin, 14 Contacts, Performance Level 2; PCB_Layout: Complies with manufacturer's recommendation.; DrillSize: Corresponds to nominal value.
footprint 918514x324 (Connector; IDC, Low Profile Male Header, Thru-Hole; 14 Position; Vertical; Pitch 2.54 mm; Body 25.40 x 9.2 x 9.45 mm (LxWxH))
pins: 1, 2, 3, 4, 5, 6, 7, 8, 9, 10, 11, 12, 13, 14

## 09 18 514 6329
designator P?
Flat Cable Connector (IDC), Standard Male Header, Straight Press-in Pin, 14 Contacts, Performance Level 2; PCB_Layout: Complies with manufacturer's recommendation.; DrillSize: Corresponds to nominal value.
footprint 918514x329 (Connector; IDC, Straight Press-in Pin, Thru-Hole; 14 Position; Vertical; Pitch 2.54 mm; Body 25.40 x 9.2 x 9.45 mm (LxWxH))
pins: 1, 2, 3, 4, 5, 6, 7, 8, 9, 10, 11, 12, 13, 14

## 09 18 514 6903
designator P?
Flat Cable Connector (IDC), Standard Male Header, Angled Solder Pin, 14 Contacts, Long Levers, Performance Level 2; PCB_Layout: Complies with manufacturer's recommendation.; DrillSize: Corresponds to nominal value.
footprint 918514x903 (Connector; IDC, Thru-Hole; 14 Position; Right Angle; Pitch 2.54 mm; Body 37.40 x 8.5 x 25.75 mm (LxHxW), Locking levers)
pins: 1, 2, 3, 4, 5, 6, 7, 8, 9, 10, 11, 12, 13, 14

## 09 18 514 6904
designator P?
Flat Cable Connector (IDC), Standard Male Header, Straight Solder Pin, 14 Contacts, Long Levers, Performance Level 2; PCB_Layout: Complies with manufacturer's recommendation.; DrillSize: Corresponds to nominal value.
footprint 918514x904 (Connector; IDC, Thru-Hole; 14 Position; Vertical; Pitch 2.54 mm; Body 37.40 x 8.5 x 25.75 mm (LxWxH), Locking levers)
pins: 1, 2, 3, 4, 5, 6, 7, 8, 9, 10, 11, 12, 13, 14

## 09 18 514 6913
designator P?
Flat Cable Connector (IDC), Standard Male Header, Angled Solder Pin, 14 Contacts, Short Levers, Performance Level 2; PCB_Layout: Complies with manufacturer's recommendation.; DrillSize: Corresponds to nominal value.
footprint 918514x913 (Connector; IDC, Thru-Hole; 14 Position; Right Angle; Pitch 2.54 mm; Body 37.40 x 8.5 x 23.30 mm (LxHxW), Locking levers)
pins: 1, 2, 3, 4, 5, 6, 7, 8, 9, 10, 11, 12, 13, 14

## 09 18 514 6914
designator P?
Flat Cable Connector (IDC), Standard Male Header, Straight Solder Pin, 14 Contacts, Short Levers, Performance Level 2; PCB_Layout: Complies with manufacturer's recommendation.; DrillSize: Corresponds to nominal value.
footprint 918514x914 (Connector; IDC, Thru-Hole; 14 Position; Vertical; Pitch 2.54 mm; Body 37.40 x 8.5 x 23.30 mm (LxWxH), Locking levers)
pins: 1, 2, 3, 4, 5, 6, 7, 8, 9, 10, 11, 12, 13, 14

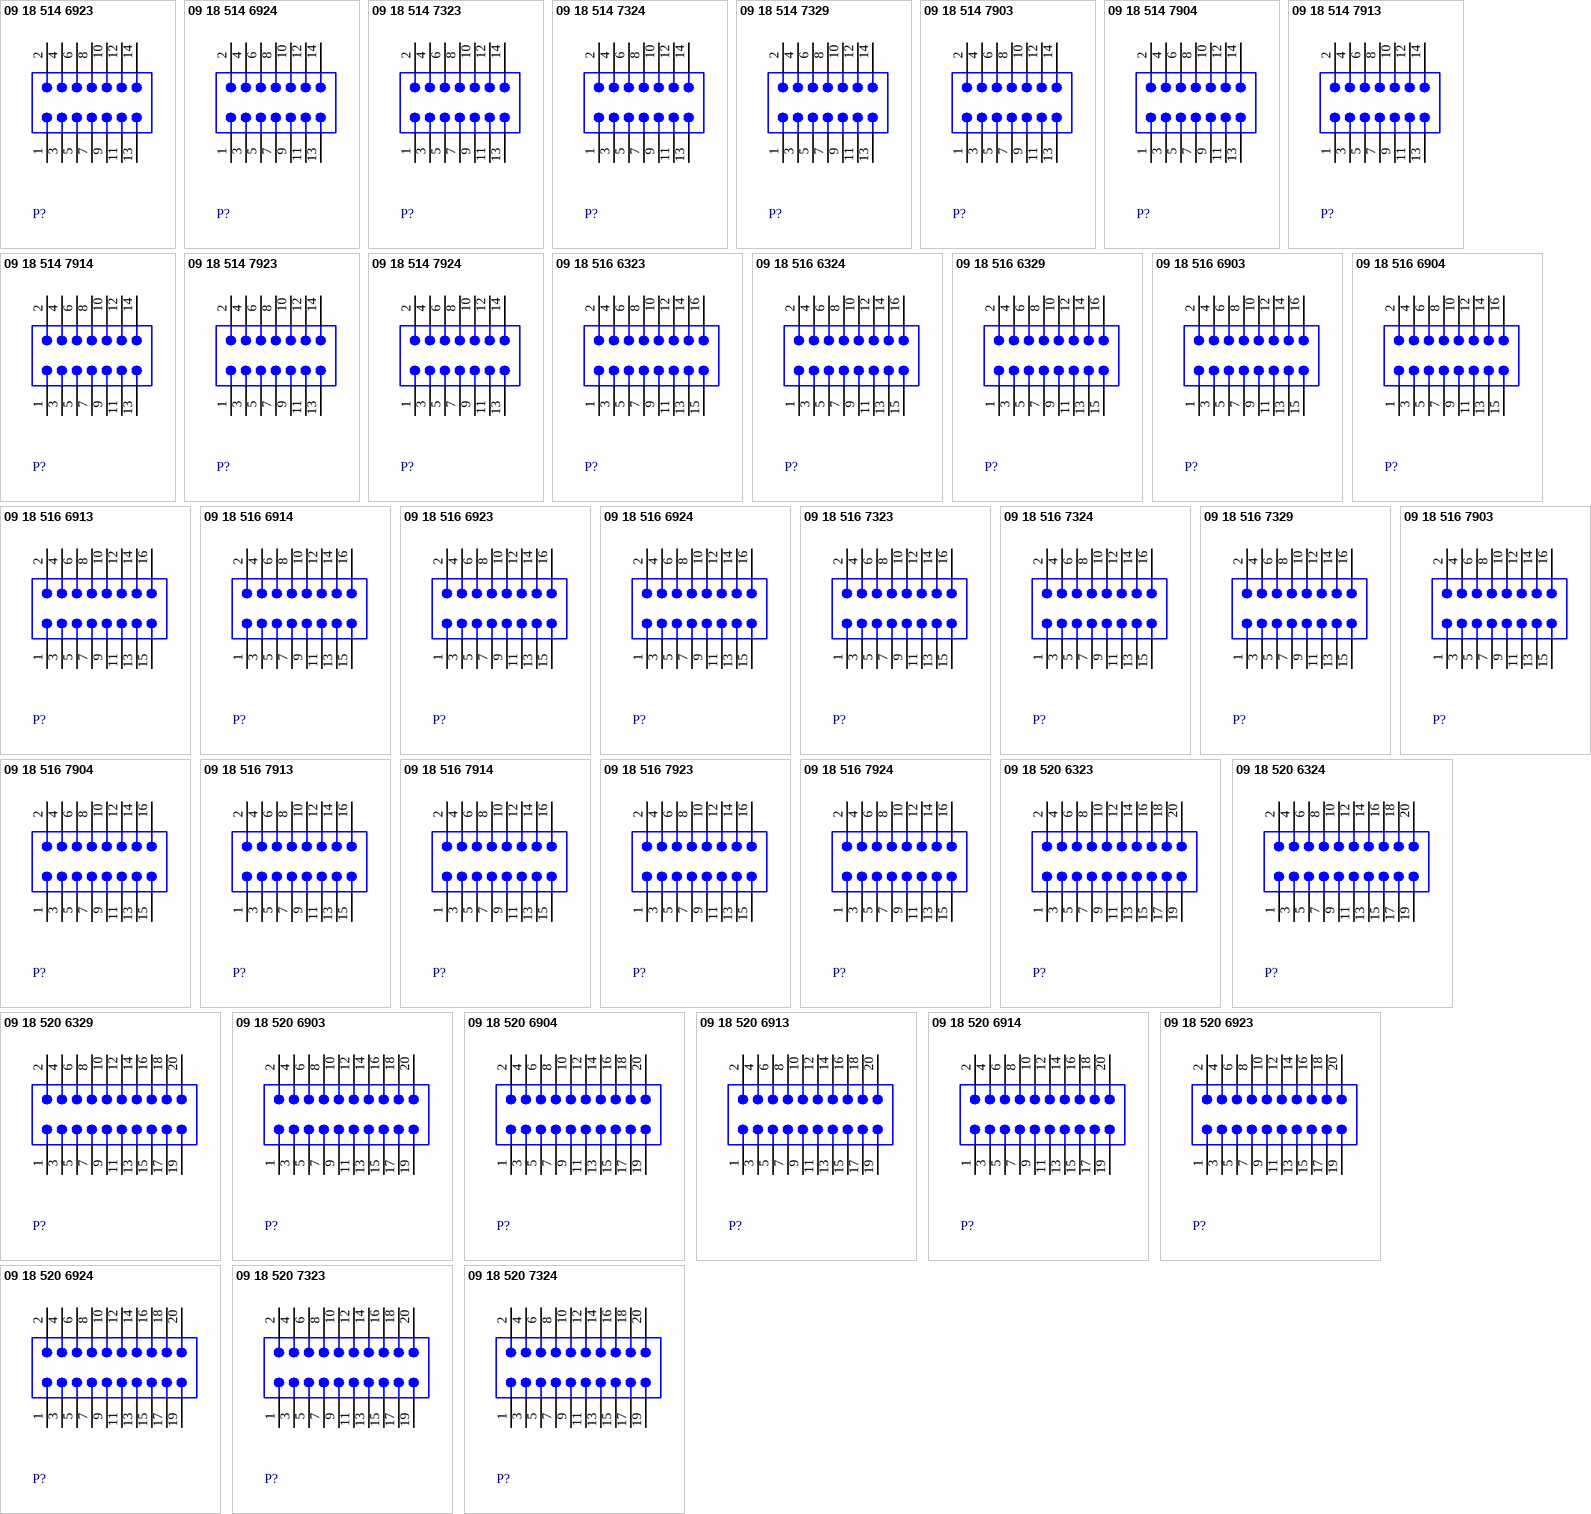
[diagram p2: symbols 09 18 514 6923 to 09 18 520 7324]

## 09 18 514 6923
designator P?
Flat Cable Connector (IDC), Standard Male Header, Angled Solder Pin, 14 Contacts, Without Levers, Performance Level 2; PCB_Layout: Complies with manufacturer's recommendation.; DrillSize: Corresponds to nominal value.
footprint 918514x923 (Connector; IDC, Thru-Hole; 14 Position; Right Angle; Pitch 2.54 mm; Body 37.40 x 8.5 x 17.30 mm (LxHxW), Without locking levers)
pins: 1, 2, 3, 4, 5, 6, 7, 8, 9, 10, 11, 12, 13, 14

## 09 18 514 6924
designator P?
Flat Cable Connector (IDC), Standard Male Header, Straight Solder Pin, 14 Contacts, Without Levers, Performance Level 2; PCB_Layout: Complies with manufacturer's recommendation.; DrillSize: Corresponds to nominal value.
footprint 918514x924 (Connector; IDC, Thru-Hole; 14 Position; Vertical; Pitch 2.54 mm; Body 37.40 x 8.5 x 17.30 mm (LxWxH), Without locking levers)
pins: 1, 2, 3, 4, 5, 6, 7, 8, 9, 10, 11, 12, 13, 14

## 09 18 514 7323
designator P?
Flat Cable Connector (IDC), Low-Profile Male Header, Angled Solder Pin, 14 Contacts, Performance Level 3; PCB_Layout: Complies with manufacturer's recommendation.; DrillSize: Corresponds to nominal value.
footprint 918514x323 (Connector; IDC, Low Profile Male Header, Thru-Hole; 14 Position; Right Angle; Pitch 2.54 mm; Body 25.40 x 8.9 x 9.2 mm (LxWxH))
pins: 1, 2, 3, 4, 5, 6, 7, 8, 9, 10, 11, 12, 13, 14

## 09 18 514 7324
designator P?
Flat Cable Connector (IDC), Low-Profile Male Header, Straight Solder Pin, 14 Contacts, Performance Level 3; PCB_Layout: Complies with manufacturer's recommendation.; DrillSize: Corresponds to nominal value.
footprint 918514x324 (Connector; IDC, Low Profile Male Header, Thru-Hole; 14 Position; Vertical; Pitch 2.54 mm; Body 25.40 x 9.2 x 9.45 mm (LxWxH))
pins: 1, 2, 3, 4, 5, 6, 7, 8, 9, 10, 11, 12, 13, 14

## 09 18 514 7329
designator P?
Flat Cable Connector (IDC), Standard Male Header, Straight Press-in Pin, 14 Contacts, Performance Level 3; PCB_Layout: Complies with manufacturer's recommendation.; DrillSize: Corresponds to nominal value.
footprint 918514x329 (Connector; IDC, Straight Press-in Pin, Thru-Hole; 14 Position; Vertical; Pitch 2.54 mm; Body 25.40 x 9.2 x 9.45 mm (LxWxH))
pins: 1, 2, 3, 4, 5, 6, 7, 8, 9, 10, 11, 12, 13, 14

## 09 18 514 7903
designator P?
Flat Cable Connector (IDC), Standard Male Header, Angled Solder Pin, 14 Contacts, Long Levers, Performance Level 3; PCB_Layout: Complies with manufacturer's recommendation.; DrillSize: Corresponds to nominal value.
footprint 918514x903 (Connector; IDC, Thru-Hole; 14 Position; Right Angle; Pitch 2.54 mm; Body 37.40 x 8.5 x 25.75 mm (LxHxW), Locking levers)
pins: 1, 2, 3, 4, 5, 6, 7, 8, 9, 10, 11, 12, 13, 14

## 09 18 514 7904
designator P?
Flat Cable Connector (IDC), Standard Male Header, Straight Solder Pin, 14 Contacts, Long Levers, Performance Level 3; PCB_Layout: Complies with manufacturer's recommendation.; DrillSize: Corresponds to nominal value.
footprint 918514x904 (Connector; IDC, Thru-Hole; 14 Position; Vertical; Pitch 2.54 mm; Body 37.40 x 8.5 x 25.75 mm (LxWxH), Locking levers)
pins: 1, 2, 3, 4, 5, 6, 7, 8, 9, 10, 11, 12, 13, 14

## 09 18 514 7913
designator P?
Flat Cable Connector (IDC), Standard Male Header, Angled Solder Pin, 14 Contacts, Short Levers, Performance Level 3; PCB_Layout: Complies with manufacturer's recommendation.; DrillSize: Corresponds to nominal value.
footprint 918514x913 (Connector; IDC, Thru-Hole; 14 Position; Right Angle; Pitch 2.54 mm; Body 37.40 x 8.5 x 23.30 mm (LxHxW), Locking levers)
pins: 1, 2, 3, 4, 5, 6, 7, 8, 9, 10, 11, 12, 13, 14

## 09 18 514 7914
designator P?
Flat Cable Connector (IDC), Standard Male Header, Straight Solder Pin, 14 Contacts, Short Levers, Performance Level 3; PCB_Layout: Complies with manufacturer's recommendation.; DrillSize: Corresponds to nominal value.
footprint 918514x914 (Connector; IDC, Thru-Hole; 14 Position; Vertical; Pitch 2.54 mm; Body 37.40 x 8.5 x 23.30 mm (LxWxH), Locking levers)
pins: 1, 2, 3, 4, 5, 6, 7, 8, 9, 10, 11, 12, 13, 14

## 09 18 514 7923
designator P?
Flat Cable Connector (IDC), Standard Male Header, Angled Solder Pin, 14 Contacts, Without Levers, Performance Level 3; PCB_Layout: Complies with manufacturer's recommendation.; DrillSize: Corresponds to nominal value.
footprint 918514x923 (Connector; IDC, Thru-Hole; 14 Position; Right Angle; Pitch 2.54 mm; Body 37.40 x 8.5 x 17.30 mm (LxHxW), Without locking levers)
pins: 1, 2, 3, 4, 5, 6, 7, 8, 9, 10, 11, 12, 13, 14

## 09 18 514 7924
designator P?
Flat Cable Connector (IDC), Standard Male Header, Straight Solder Pin, 14 Contacts, Without Levers, Performance Level 3; PCB_Layout: Complies with manufacturer's recommendation.; DrillSize: Corresponds to nominal value.
footprint 918514x924 (Connector; IDC, Thru-Hole; 14 Position; Vertical; Pitch 2.54 mm; Body 37.40 x 8.5 x 17.30 mm (LxWxH), Without locking levers)
pins: 1, 2, 3, 4, 5, 6, 7, 8, 9, 10, 11, 12, 13, 14

## 09 18 516 6323
designator P?
Flat Cable Connector (IDC), Low-Profile Male Header, Angled Solder Pin, 16 Contacts, Performance Level 2; PCB_Layout: Complies with manufacturer's recommendation.; DrillSize: Corresponds to nominal value.
footprint 918516x323 (Connector; IDC, Low Profile Male Header, Thru-Hole; 16 Position; Right Angle; Pitch 2.54 mm; Body 27.94 x 8.9 x 9.2 mm (LxWxH))
pins: 1, 2, 3, 4, 5, 6, 7, 8, 9, 10, 11, 12, 13, 14, 15, 16

## 09 18 516 6324
designator P?
Flat Cable Connector (IDC), Low-Profile Male Header, Straight Solder Pin, 16 Contacts, Performance Level 2; PCB_Layout: Complies with manufacturer's recommendation.; DrillSize: Corresponds to nominal value.
footprint 918516x324 (Connector; IDC, Low Profile Male Header, Thru-Hole; 16 Position; Vertical; Pitch 2.54 mm; Body 27.94 x 9.2 x 9.45 mm (LxWxH))
pins: 1, 2, 3, 4, 5, 6, 7, 8, 9, 10, 11, 12, 13, 14, 15, 16

## 09 18 516 6329
designator P?
Flat Cable Connector (IDC), Standard Male Header, Straight Press-in Pin, 16 Contacts, Performance Level 2; PCB_Layout: Complies with manufacturer's recommendation.; DrillSize: Corresponds to nominal value.
footprint 918516x329 (Connector; IDC, Straight Press-in Pin, Thru-Hole; 16 Position; Vertical; Pitch 2.54 mm; Body 27.94 x 9.2 x 9.45 mm (LxWxH))
pins: 1, 2, 3, 4, 5, 6, 7, 8, 9, 10, 11, 12, 13, 14, 15, 16

## 09 18 516 6903
designator P?
Flat Cable Connector (IDC), Standard Male Header, Angled Solder Pin, 16 Contacts, Long Levers, Performance Level 2; PCB_Layout: Complies with manufacturer's recommendation.; DrillSize: Corresponds to nominal value.
footprint 918516x903 (Connector; IDC, Thru-Hole; 16 Position; Right Angle; Pitch 2.54 mm; Body 39.90 x 8.5 x 25.75 mm (LxHxW), Locking levers)
pins: 1, 2, 3, 4, 5, 6, 7, 8, 9, 10, 11, 12, 13, 14, 15, 16

## 09 18 516 6904
designator P?
Flat Cable Connector (IDC), Standard Male Header, Straight Solder Pin, 16 Contacts, Long Levers, Performance Level 2; PCB_Layout: Complies with manufacturer's recommendation.; DrillSize: Corresponds to nominal value.
footprint 918516x904 (Connector; IDC, Thru-Hole; 16 Position; Vertical; Pitch 2.54 mm; Body 39.90 x 8.5 x 25.75 mm (LxWxH), Locking levers)
pins: 1, 2, 3, 4, 5, 6, 7, 8, 9, 10, 11, 12, 13, 14, 15, 16

## 09 18 516 6913
designator P?
Flat Cable Connector (IDC), Standard Male Header, Angled Solder Pin, 16 Contacts, Short Levers, Performance Level 2; PCB_Layout: Complies with manufacturer's recommendation.; DrillSize: Corresponds to nominal value.
footprint 918516x913 (Connector; IDC, Thru-Hole; 16 Position; Right Angle; Pitch 2.54 mm; Body 39.90 x 8.5 x 23.30 mm (LxHxW), Locking levers)
pins: 1, 2, 3, 4, 5, 6, 7, 8, 9, 10, 11, 12, 13, 14, 15, 16

## 09 18 516 6914
designator P?
Flat Cable Connector (IDC), Standard Male Header, Straight Solder Pin, 16 Contacts, Short Levers, Performance Level 2; PCB_Layout: Complies with manufacturer's recommendation.; DrillSize: Corresponds to nominal value.
footprint 918516x914 (Connector; IDC, Thru-Hole; 16 Position; Vertical; Pitch 2.54 mm; Body 39.90 x 8.5 x 23.30 mm (LxWxH), Locking levers)
pins: 1, 2, 3, 4, 5, 6, 7, 8, 9, 10, 11, 12, 13, 14, 15, 16

## 09 18 516 6923
designator P?
Flat Cable Connector (IDC), Standard Male Header, Angled Solder Pin, 16 Contacts, Without Levers, Performance Level 2; PCB_Layout: Complies with manufacturer's recommendation.; DrillSize: Corresponds to nominal value.
footprint 918516x923 (Connector; IDC, Thru-Hole; 16 Position; Right Angle; Pitch 2.54 mm; Body 39.90 x 8.5 x 17.30 mm (LxHxW), Without locking levers)
pins: 1, 2, 3, 4, 5, 6, 7, 8, 9, 10, 11, 12, 13, 14, 15, 16

## 09 18 516 6924
designator P?
Flat Cable Connector (IDC), Standard Male Header, Straight Solder Pin, 16 Contacts, Without Levers, Performance Level 2; PCB_Layout: Complies with manufacturer's recommendation.; DrillSize: Corresponds to nominal value.
footprint 918516x924 (Connector; IDC, Thru-Hole; 16 Position; Vertical; Pitch 2.54 mm; Body 39.90 x 8.5 x 17.30 mm (LxWxH), Without locking levers)
pins: 1, 2, 3, 4, 5, 6, 7, 8, 9, 10, 11, 12, 13, 14, 15, 16

## 09 18 516 7323
designator P?
Flat Cable Connector (IDC), Low-Profile Male Header, Angled Solder Pin, 16 Contacts, Performance Level 3; PCB_Layout: Complies with manufacturer's recommendation.; DrillSize: Corresponds to nominal value.
footprint 918516x323 (Connector; IDC, Low Profile Male Header, Thru-Hole; 16 Position; Right Angle; Pitch 2.54 mm; Body 27.94 x 8.9 x 9.2 mm (LxWxH))
pins: 1, 2, 3, 4, 5, 6, 7, 8, 9, 10, 11, 12, 13, 14, 15, 16

## 09 18 516 7324
designator P?
Flat Cable Connector (IDC), Low-Profile Male Header, Straight Solder Pin, 16 Contacts, Performance Level 3; PCB_Layout: Complies with manufacturer's recommendation.; DrillSize: Corresponds to nominal value.
footprint 918516x324 (Connector; IDC, Low Profile Male Header, Thru-Hole; 16 Position; Vertical; Pitch 2.54 mm; Body 27.94 x 9.2 x 9.45 mm (LxWxH))
pins: 1, 2, 3, 4, 5, 6, 7, 8, 9, 10, 11, 12, 13, 14, 15, 16

## 09 18 516 7329
designator P?
Flat Cable Connector (IDC), Standard Male Header, Straight Press-in Pin, 16 Contacts, Performance Level 3; PCB_Layout: Complies with manufacturer's recommendation.; DrillSize: Corresponds to nominal value.
footprint 918516x329 (Connector; IDC, Straight Press-in Pin, Thru-Hole; 16 Position; Vertical; Pitch 2.54 mm; Body 27.94 x 9.2 x 9.45 mm (LxWxH))
pins: 1, 2, 3, 4, 5, 6, 7, 8, 9, 10, 11, 12, 13, 14, 15, 16

## 09 18 516 7903
designator P?
Flat Cable Connector (IDC), Standard Male Header, Angled Solder Pin, 16 Contacts, Long Levers, Performance Level 3; PCB_Layout: Complies with manufacturer's recommendation.; DrillSize: Corresponds to nominal value.
footprint 918516x903 (Connector; IDC, Thru-Hole; 16 Position; Right Angle; Pitch 2.54 mm; Body 39.90 x 8.5 x 25.75 mm (LxHxW), Locking levers)
pins: 1, 2, 3, 4, 5, 6, 7, 8, 9, 10, 11, 12, 13, 14, 15, 16

## 09 18 516 7904
designator P?
Flat Cable Connector (IDC), Standard Male Header, Straight Solder Pin, 16 Contacts, Long Levers, Performance Level 3; PCB_Layout: Complies with manufacturer's recommendation.; DrillSize: Corresponds to nominal value.
footprint 918516x904 (Connector; IDC, Thru-Hole; 16 Position; Vertical; Pitch 2.54 mm; Body 39.90 x 8.5 x 25.75 mm (LxWxH), Locking levers)
pins: 1, 2, 3, 4, 5, 6, 7, 8, 9, 10, 11, 12, 13, 14, 15, 16

## 09 18 516 7913
designator P?
Flat Cable Connector (IDC), Standard Male Header, Angled Solder Pin, 16 Contacts, Short Levers, Performance Level 3; PCB_Layout: Complies with manufacturer's recommendation.; DrillSize: Corresponds to nominal value.
footprint 918516x913 (Connector; IDC, Thru-Hole; 16 Position; Right Angle; Pitch 2.54 mm; Body 39.90 x 8.5 x 23.30 mm (LxHxW), Locking levers)
pins: 1, 2, 3, 4, 5, 6, 7, 8, 9, 10, 11, 12, 13, 14, 15, 16

## 09 18 516 7914
designator P?
Flat Cable Connector (IDC), Standard Male Header, Straight Solder Pin, 16 Contacts, Short Levers, Performance Level 3; PCB_Layout: Complies with manufacturer's recommendation.; DrillSize: Corresponds to nominal value.
footprint 918516x914 (Connector; IDC, Thru-Hole; 16 Position; Vertical; Pitch 2.54 mm; Body 39.90 x 8.5 x 23.30 mm (LxWxH), Locking levers)
pins: 1, 2, 3, 4, 5, 6, 7, 8, 9, 10, 11, 12, 13, 14, 15, 16

## 09 18 516 7923
designator P?
Flat Cable Connector (IDC), Standard Male Header, Angled Solder Pin, 16 Contacts, Without Levers, Performance Level 3; PCB_Layout: Complies with manufacturer's recommendation.; DrillSize: Corresponds to nominal value.
footprint 918516x923 (Connector; IDC, Thru-Hole; 16 Position; Right Angle; Pitch 2.54 mm; Body 39.90 x 8.5 x 17.30 mm (LxHxW), Without locking levers)
pins: 1, 2, 3, 4, 5, 6, 7, 8, 9, 10, 11, 12, 13, 14, 15, 16

## 09 18 516 7924
designator P?
Flat Cable Connector (IDC), Standard Male Header, Straight Solder Pin, 16 Contacts, Without Levers, Performance Level 3; PCB_Layout: Complies with manufacturer's recommendation.; DrillSize: Corresponds to nominal value.
footprint 918516x924 (Connector; IDC, Thru-Hole; 16 Position; Vertical; Pitch 2.54 mm; Body 39.90 x 8.5 x 17.30 mm (LxWxH), Without locking levers)
pins: 1, 2, 3, 4, 5, 6, 7, 8, 9, 10, 11, 12, 13, 14, 15, 16

## 09 18 520 6323
designator P?
Flat Cable Connector (IDC), Low-Profile Male Header, Angled Solder Pin, 20 Contacts, Performance Level 2; PCB_Layout: Complies with manufacturer's recommendation.; DrillSize: Corresponds to nominal value.
footprint 918520x323 (Connector; IDC, Low Profile Male Header, Thru-Hole; 20 Position; Right Angle; Pitch 2.54 mm; Body 33.02 x 8.9 x 9.2 mm (LxWxH))
pins: 1, 2, 3, 4, 5, 6, 7, 8, 9, 10, 11, 12, 13, 14, 15, 16, 17, 18, 19, 20

## 09 18 520 6324
designator P?
Flat Cable Connector (IDC), Low-Profile Male Header, Straight Solder Pin, 20 Contacts, Performance Level 2; PCB_Layout: Complies with manufacturer's recommendation.; DrillSize: Corresponds to nominal value.
footprint 918520x324 (Connector; IDC, Low Profile Male Header, Thru-Hole; 20 Position; Vertical; Pitch 2.54 mm; Body 33.02 x 9.2 x 9.45 mm (LxWxH))
pins: 1, 2, 3, 4, 5, 6, 7, 8, 9, 10, 11, 12, 13, 14, 15, 16, 17, 18, 19, 20

## 09 18 520 6329
designator P?
Flat Cable Connector (IDC), Standard Male Header, Straight Press-in Pin, 20 Contacts, Performance Level 2; PCB_Layout: Complies with manufacturer's recommendation.; DrillSize: Corresponds to nominal value.
footprint 918520x329 (Connector; IDC, Straight Press-in Pin, Thru-Hole; 20 Position; Vertical; Pitch 2.54 mm; Body 33.02 x 9.2 x 9.45 mm (LxWxH))
pins: 1, 2, 3, 4, 5, 6, 7, 8, 9, 10, 11, 12, 13, 14, 15, 16, 17, 18, 19, 20

## 09 18 520 6903
designator P?
Flat Cable Connector (IDC), Standard Male Header, Angled Solder Pin, 20 Contacts, Long Levers, Performance Level 2; PCB_Layout: Complies with manufacturer's recommendation.; DrillSize: Corresponds to nominal value.
footprint 918520x903 (Connector; IDC, Thru-Hole; 20 Position; Right Angle; Pitch 2.54 mm; Body 45.00 x 8.5 x 25.75 mm (LxHxW), Locking levers)
pins: 1, 2, 3, 4, 5, 6, 7, 8, 9, 10, 11, 12, 13, 14, 15, 16, 17, 18, 19, 20

## 09 18 520 6904
designator P?
Flat Cable Connector (IDC), Standard Male Header, Straight Solder Pin, 20 Contacts, Long Levers, Performance Level 2; PCB_Layout: Complies with manufacturer's recommendation.; DrillSize: Corresponds to nominal value.
footprint 918520x904 (Connector; IDC, Thru-Hole; 20 Position; Vertical; Pitch 2.54 mm; Body 45.00 x 8.5 x 25.75 mm (LxWxH), Locking levers)
pins: 1, 2, 3, 4, 5, 6, 7, 8, 9, 10, 11, 12, 13, 14, 15, 16, 17, 18, 19, 20

## 09 18 520 6913
designator P?
Flat Cable Connector (IDC), Standard Male Header, Angled Solder Pin, 20 Contacts, Short Levers, Performance Level 2; PCB_Layout: Complies with manufacturer's recommendation.; DrillSize: Corresponds to nominal value.
footprint 918520x913 (Connector; IDC, Thru-Hole; 20 Position; Right Angle; Pitch 2.54 mm; Body 45.00 x 8.5 x 23.30 mm (LxHxW), Locking levers)
pins: 1, 2, 3, 4, 5, 6, 7, 8, 9, 10, 11, 12, 13, 14, 15, 16, 17, 18, 19, 20

## 09 18 520 6914
designator P?
Flat Cable Connector (IDC), Standard Male Header, Straight Solder Pin, 20 Contacts, Short Levers, Performance Level 2; PCB_Layout: Complies with manufacturer's recommendation.; DrillSize: Corresponds to nominal value.
footprint 918520x914 (Connector; IDC, Thru-Hole; 20 Position; Vertical; Pitch 2.54 mm; Body 45.00 x 8.5 x 23.30 mm (LxWxH), Locking levers)
pins: 1, 2, 3, 4, 5, 6, 7, 8, 9, 10, 11, 12, 13, 14, 15, 16, 17, 18, 19, 20

## 09 18 520 6923
designator P?
Flat Cable Connector (IDC), Standard Male Header, Angled Solder Pin, 20 Contacts, Without Levers, Performance Level 2; PCB_Layout: Complies with manufacturer's recommendation.; DrillSize: Corresponds to nominal value.
footprint 918520x923 (Connector; IDC, Thru-Hole; 20 Position; Right Angle; Pitch 2.54 mm; Body 45.00 x 8.5 x 17.30 mm (LxHxW), Without locking levers)
pins: 1, 2, 3, 4, 5, 6, 7, 8, 9, 10, 11, 12, 13, 14, 15, 16, 17, 18, 19, 20

## 09 18 520 6924
designator P?
Flat Cable Connector (IDC), Standard Male Header, Straight Solder Pin, 20 Contacts, Without Levers, Performance Level 2; PCB_Layout: Complies with manufacturer's recommendation.; DrillSize: Corresponds to nominal value.
footprint 918520x924 (Connector; IDC, Thru-Hole; 20 Position; Vertical; Pitch 2.54 mm; Body 45.00 x 8.5 x 17.30 mm (LxWxH), Without locking levers)
pins: 1, 2, 3, 4, 5, 6, 7, 8, 9, 10, 11, 12, 13, 14, 15, 16, 17, 18, 19, 20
